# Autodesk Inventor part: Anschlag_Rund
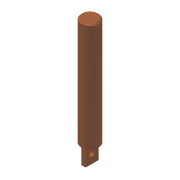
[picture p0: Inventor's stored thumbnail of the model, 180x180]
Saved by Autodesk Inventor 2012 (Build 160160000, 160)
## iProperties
Company: CAD-Verlag
Created: 2004-09
Part Number: Anschlag_Rund
Document SubType Name: Modeling
Designer: Greiling
Manufacturer: Standard
Standards Organization: Custom
Density: 8.94 g/cm^3
Material: Kupfer
Mass: 2878.48 g
Surface Area: 367.961 cm^2
Volume: 321.978 cm^3
Checked By: Jürgen Kronas
Stock Number: 10-10013
Author: Juergen Kronas
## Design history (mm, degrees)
sketch "Skizze1"
  geometry: L1 (0, 28)-(0, -28) reference; L2 (-28, 0)-(28, 0) reference; L3 (-28, 0)-(28, 0) reference; L4 (0, -28)-(0, 28) reference; C1 r 20 at (0, 0); 1 further point
  constraints: 1 centre point, 1 coincident
  dimensions: "d0" = 40 diameter of C1
extrude "Extrusion1" new body sketch "Skizze1" distance "d1" = 248; taper "d2" = 0 deg
chamfer "Fase1" distance "d3" = 3; stored, may be unused: second distance "d4" = 2, angle "d5" = 45 deg
sketch "Skizze2"
  geometry: L1 (-5, 15)-(5, 15); L2 (5, 15)-(5, -15); L3 (5, -15)-(-5, -15); L4 (-5, -15)-(-5, 15); L5 (0, -28)-(0, 28) reference; L6 (-28, 0)-(28, 0) reference; L7 (28, 0)-(-28, 0) reference; L8 (0, -28)-(0, 28) reference
  constraints: 8 end point, 2 parallel, 1 horizontal, 1 perpendicular, 2 other
  dimensions: "d6" = 10 distance of L1.start L1.end; "d7" = 30 distance of L3.end L1.start
extrude "Extrusion2" join sketch "Skizze2" distance "d8" = 40; taper "d9" = 0 deg
sketch "Skizze3"
  geometry: L1 (0, 0)-(0, 30) reference; L2 (-345.6, 15)-(57.6, 15) reference; L3 (-40, -13)-(-40, 43) reference; C1 r 6 at (-20, 15); 1 further point
  constraints: 1 centre point, 1 point on line
  dimensions: "d10" = 20 distance from line of L1 C1.centre; "d11" = 12 diameter of C1
extrude "Extrusion3" cut sketch "Skizze3" stored distance "d12" = 40; taper "d13" = 0 deg
node "Volumenkörper1"
node "Volumenkörpern"
node "Oberflächenkörpern"
